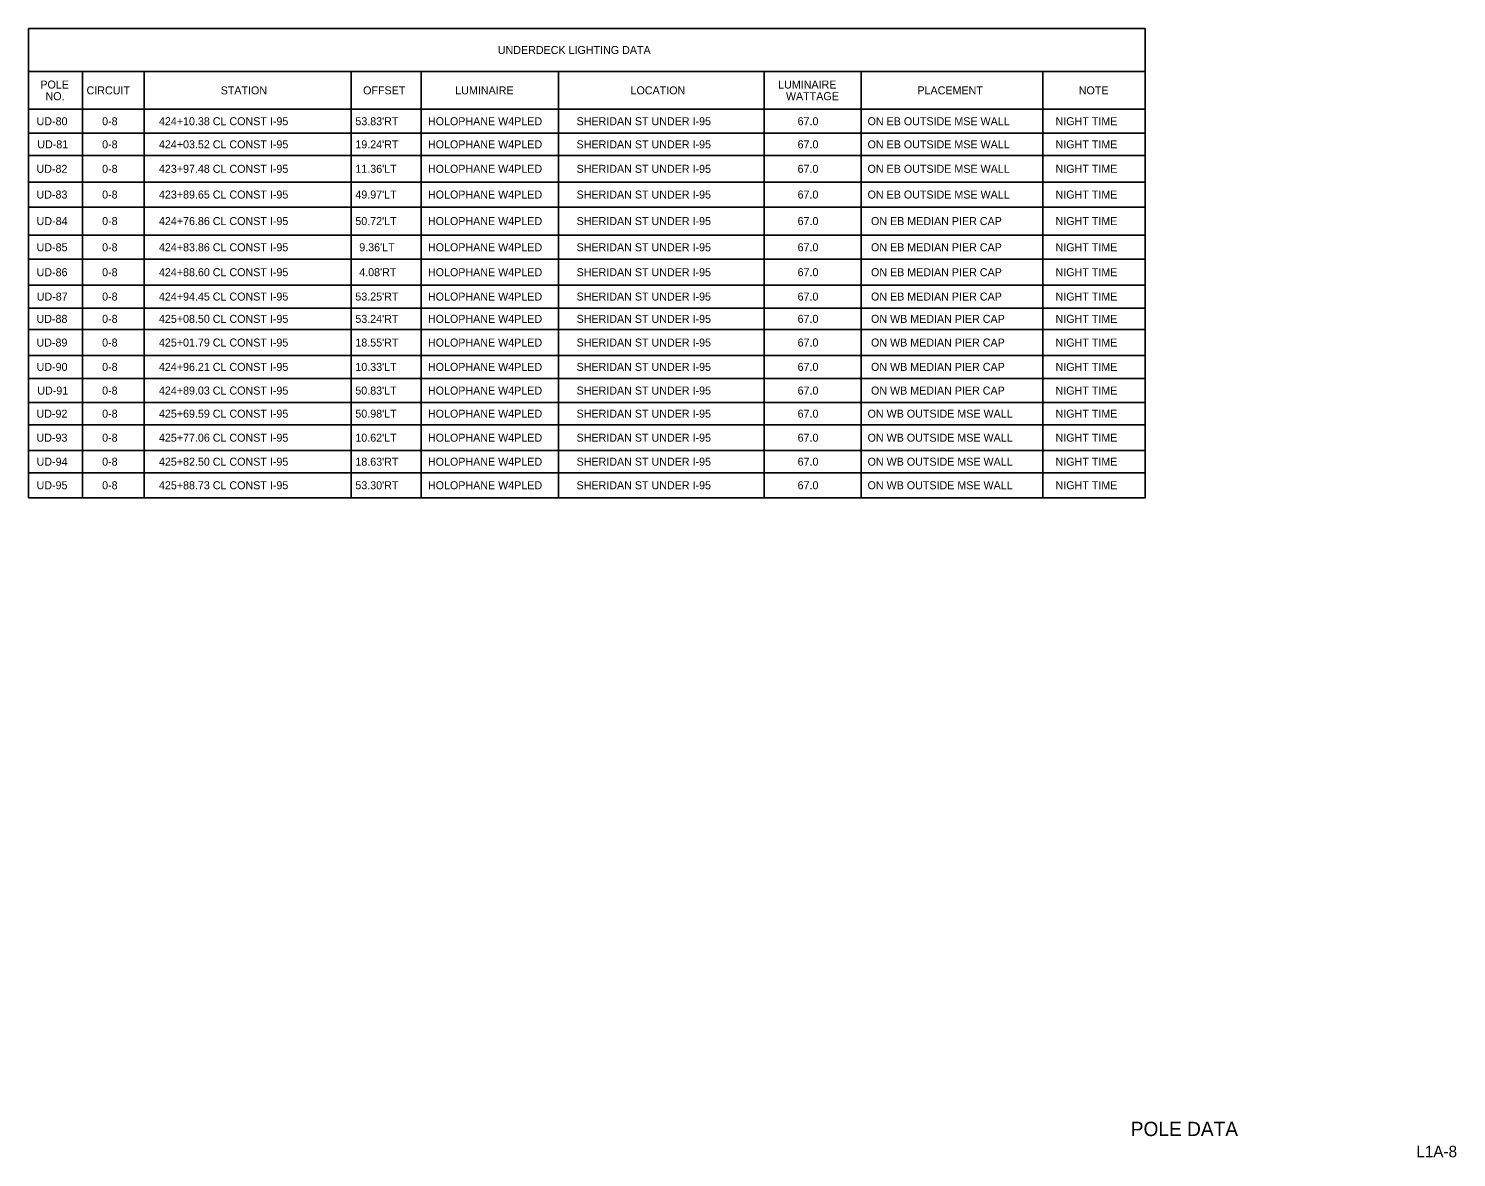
# Model space of a CAD drawing. Extents: x -816.7 to -727.6, y -2197.9 to -2187.8.
# Drawn here: x -740.07 to -727.59, y -2197.64 to -2187.77 of the extents above; entities that cross this region are included whole.
import ezdxf

# ---------------------------------------------------------------- set-up
doc = ezdxf.new("R2010")
doc.units = 0
for name, color, linetype in [('ClipBorder_dp', 7, 'Continuous'), ('MatchLines_dp', 7, 'Continuous'), ('NorthArw_dp', 7, 'Continuous'), ('Scale_dp', 7, 'Continuous'), ('SignWorkZone', 7, 'Continuous'), ('TextLabel', 7, 'Continuous')]:
    doc.layers.add(name, color=color, linetype=linetype)

msp = doc.modelspace()

# ---------------------------------------------------------------- linework, layer by layer
at = {"layer": 'MatchLines_dp'}
for p, q in [((-740.074, -2188.479), (-730.309, -2188.479)), ((-740.074, -2188.689), (-730.309, -2188.689)), ((-740.074, -2188.689), (-730.309, -2188.689)), ((-740.074, -2188.884), (-730.309, -2188.884)), ((-740.074, -2188.884), (-730.309, -2188.884)), ((-740.074, -2189.116), (-730.309, -2189.116)), ((-740.074, -2189.116), (-730.309, -2189.116)), ((-740.074, -2189.334), (-730.309, -2189.334)), ((-740.074, -2189.334), (-730.309, -2189.334)), ((-740.074, -2189.581), (-730.309, -2189.581)), ((-740.074, -2189.581), (-730.309, -2189.581)), ((-740.074, -2189.791), (-730.309, -2189.791)), ((-740.074, -2189.791), (-730.309, -2189.791)), ((-740.074, -2190.016), (-730.309, -2190.016)), ((-740.074, -2190.016), (-730.309, -2190.016)), ((-740.074, -2190.219), (-730.309, -2190.219)), ((-740.074, -2190.219), (-730.309, -2190.219)), ((-740.074, -2190.406), (-730.309, -2190.406)), ((-740.074, -2190.406), (-730.309, -2190.406)), ((-740.074, -2190.631), (-730.309, -2190.631)), ((-740.074, -2190.631), (-730.309, -2190.631)), ((-740.074, -2190.834), (-730.309, -2190.834)), ((-740.074, -2190.834), (-730.309, -2190.834)), ((-740.074, -2191.044), (-730.309, -2191.044)), ((-740.074, -2191.044), (-730.309, -2191.044)), ((-740.074, -2191.239), (-730.309, -2191.239)), ((-740.074, -2191.239), (-730.309, -2191.239)), ((-740.074, -2191.464), (-730.309, -2191.464)), ((-740.074, -2191.464), (-730.309, -2191.464)), ((-740.074, -2191.659), (-730.309, -2191.659)), ((-740.074, -2191.659), (-730.309, -2191.659))]:
    msp.add_line(p, q, dxfattribs=at)
at = {"layer": 'NorthArw_dp'}
for p, q in [((-740.074, -2187.774), (-730.309, -2187.774)), ((-740.074, -2187.774), (-740.074, -2191.876)), ((-730.309, -2187.774), (-730.309, -2191.876)), ((-740.074, -2188.149), (-730.309, -2188.149)), ((-740.074, -2188.149), (-730.309, -2188.149)), ((-731.202, -2188.149), (-731.202, -2191.876)), ((-731.202, -2188.479), (-731.202, -2191.876)), ((-740.074, -2191.876), (-730.309, -2191.876))]:
    msp.add_line(p, q, dxfattribs=at)
at = {"layer": 'Scale_dp'}
for p, q in [((-739.602, -2188.149), (-739.602, -2191.876)), ((-739.602, -2188.149), (-739.602, -2191.876)), ((-739.062, -2188.149), (-739.062, -2191.876)), ((-739.062, -2188.149), (-739.062, -2191.876)), ((-737.254, -2188.149), (-737.254, -2191.876)), ((-737.254, -2188.149), (-737.254, -2191.876)), ((-736.639, -2188.149), (-736.639, -2191.876)), ((-736.639, -2188.149), (-736.639, -2191.876)), ((-735.439, -2188.149), (-735.439, -2191.876)), ((-735.439, -2188.149), (-735.439, -2191.876)), ((-733.639, -2188.149), (-733.639, -2191.876)), ((-733.639, -2188.149), (-733.639, -2191.876)), ((-732.792, -2188.149), (-732.792, -2191.876)), ((-732.792, -2188.149), (-732.792, -2191.876)), ((-731.202, -2188.149), (-731.202, -2188.479)), ((-740.074, -2188.479), (-730.309, -2188.479))]:
    msp.add_line(p, q, dxfattribs=at)

# ---------------------------------------------------------------- texts
at = {"layer": 'ClipBorder_dp'}
for s, p in [('UNDERDECK LIGHTING DATA', (-735.97, -2187.996)), ('POLE', (-739.971, -2188.298)), ('LUMINAIRE', (-733.518, -2188.298)), ('NO.', (-739.926, -2188.4)), ('CIRCUIT', (-739.567, -2188.349)), ('STATION', (-738.394, -2188.349)), ('OFFSET', (-737.148, -2188.349)), ('LUMINAIRE', (-736.342, -2188.349)), ('LOCATION', (-734.809, -2188.349)), ('WATTAGE', (-733.45, -2188.4)), ('PLACEMENT', (-732.3, -2188.349)), ('NOTE', (-730.889, -2188.349)), ('UD-80', (-740.004, -2188.619)), ('0-8', (-739.431, -2188.619)), ('424+10.38 CL CONST I-95', (-738.934, -2188.619)), ("53.83'RT", (-737.216, -2188.619)), ('HOLOPHANE W4PLED', (-736.581, -2188.619)), ('SHERIDAN ST UNDER I-95', (-735.281, -2188.619)), ('67.0', (-733.348, -2188.619)), ('ON EB OUTSIDE MSE WALL', (-732.736, -2188.619)), ('NIGHT TIME', (-731.092, -2188.619)), ('UD-81', (-739.998, -2188.821)), ('0-8', (-739.431, -2188.821)), ('424+03.52 CL CONST I-95', (-738.934, -2188.821)), ("19.24'RT", (-737.216, -2188.821)), ('HOLOPHANE W4PLED', (-736.581, -2188.821)), ('SHERIDAN ST UNDER I-95', (-735.281, -2188.821)), ('67.0', (-733.348, -2188.821)), ('ON EB OUTSIDE MSE WALL', (-732.736, -2188.821)), ('NIGHT TIME', (-731.092, -2188.821)), ('UD-82', (-740.005, -2189.035)), ('0-8', (-739.431, -2189.035)), ('423+97.48 CL CONST I-95', (-738.934, -2189.035)), ("11.36'LT", (-737.216, -2189.035)), ('HOLOPHANE W4PLED', (-736.581, -2189.035)), ('SHERIDAN ST UNDER I-95', (-735.281, -2189.035)), ('67.0', (-733.348, -2189.035)), ('ON EB OUTSIDE MSE WALL', (-732.736, -2189.035)), ('NIGHT TIME', (-731.092, -2189.035)), ('UD-83', (-740.005, -2189.26)), ('0-8', (-739.431, -2189.26)), ('423+89.65 CL CONST I-95', (-738.934, -2189.26)), ("49.97'LT", (-737.216, -2189.26)), ('HOLOPHANE W4PLED', (-736.581, -2189.26)), ('SHERIDAN ST UNDER I-95', (-735.281, -2189.26)), ('67.0', (-733.348, -2189.26)), ('ON EB OUTSIDE MSE WALL', (-732.736, -2189.26)), ('NIGHT TIME', (-731.092, -2189.26)), ('UD-84', (-740.004, -2189.492)), ('0-8', (-739.431, -2189.492)), ('424+76.86 CL CONST I-95', (-738.934, -2189.492)), ("50.72'LT", (-737.216, -2189.492)), ('HOLOPHANE W4PLED', (-736.581, -2189.492)), ('SHERIDAN ST UNDER I-95', (-735.281, -2189.492)), ('67.0', (-733.348, -2189.492)), ('ON EB MEDIAN PIER CAP', (-732.706, -2189.492)), ('NIGHT TIME', (-731.092, -2189.492)), ('UD-85', (-740.004, -2189.721)), ('0-8', (-739.431, -2189.721)), ('424+83.86 CL CONST I-95', (-738.934, -2189.721)), ("9.36'LT", (-737.182, -2189.721)), ('HOLOPHANE W4PLED', (-736.581, -2189.721)), ('SHERIDAN ST UNDER I-95', (-735.281, -2189.721)), ('67.0', (-733.348, -2189.721)), ('ON EB MEDIAN PIER CAP', (-732.706, -2189.721)), ('NIGHT TIME', (-731.092, -2189.721)), ('UD-86', (-740.004, -2189.939)), ('0-8', (-739.431, -2189.939)), ('424+88.60 CL CONST I-95', (-738.934, -2189.939)), ("4.08'RT", (-737.182, -2189.939)), ('HOLOPHANE W4PLED', (-736.581, -2189.939)), ('SHERIDAN ST UNDER I-95', (-735.281, -2189.939)), ('67.0', (-733.348, -2189.939)), ('ON EB MEDIAN PIER CAP', (-732.706, -2189.939)), ('NIGHT TIME', (-731.092, -2189.939)), ('UD-87', (-740.003, -2190.152)), ('0-8', (-739.431, -2190.152)), ('424+94.45 CL CONST I-95', (-738.934, -2190.152)), ("53.25'RT", (-737.216, -2190.152)), ('HOLOPHANE W4PLED', (-736.581, -2190.152)), ('SHERIDAN ST UNDER I-95', (-735.281, -2190.152)), ('67.0', (-733.348, -2190.152)), ('ON EB MEDIAN PIER CAP', (-732.706, -2190.152)), ('NIGHT TIME', (-731.092, -2190.152)), ('UD-88', (-740.005, -2190.347)), ('0-8', (-739.431, -2190.347)), ('425+08.50 CL CONST I-95', (-738.934, -2190.347)), ("53.24'RT", (-737.216, -2190.347)), ('HOLOPHANE W4PLED', (-736.581, -2190.347)), ('SHERIDAN ST UNDER I-95', (-735.281, -2190.347)), ('67.0', (-733.348, -2190.347)), ('ON WB MEDIAN PIER CAP', (-732.706, -2190.347)), ('NIGHT TIME', (-731.092, -2190.347)), ('UD-89', (-740.005, -2190.554)), ('0-8', (-739.431, -2190.554)), ('425+01.79 CL CONST I-95', (-738.934, -2190.554)), ("18.55'RT", (-737.216, -2190.554)), ('HOLOPHANE W4PLED', (-736.581, -2190.554)), ('SHERIDAN ST UNDER I-95', (-735.281, -2190.554)), ('67.0', (-733.348, -2190.554)), ('ON WB MEDIAN PIER CAP', (-732.706, -2190.554)), ('NIGHT TIME', (-731.092, -2190.554)), ('UD-90', (-740.004, -2190.767)), ('0-8', (-739.431, -2190.767)), ('424+96.21 CL CONST I-95', (-738.934, -2190.767)), ("10.33'LT", (-737.216, -2190.767)), ('HOLOPHANE W4PLED', (-736.581, -2190.767)), ('SHERIDAN ST UNDER I-95', (-735.281, -2190.767)), ('67.0', (-733.348, -2190.767)), ('ON WB MEDIAN PIER CAP', (-732.706, -2190.767)), ('NIGHT TIME', (-731.092, -2190.767)), ('UD-91', (-739.998, -2190.974)), ('0-8', (-739.431, -2190.974)), ('424+89.03 CL CONST I-95', (-738.934, -2190.974)), ("50.83'LT", (-737.216, -2190.974)), ('HOLOPHANE W4PLED', (-736.581, -2190.974)), ('SHERIDAN ST UNDER I-95', (-735.281, -2190.974)), ('67.0', (-733.348, -2190.974)), ('ON WB MEDIAN PIER CAP', (-732.706, -2190.974)), ('NIGHT TIME', (-731.092, -2190.974)), ('UD-92', (-740.005, -2191.176)), ('0-8', (-739.431, -2191.176)), ('425+69.59 CL CONST I-95', (-738.934, -2191.176)), ("50.98'LT", (-737.216, -2191.176)), ('HOLOPHANE W4PLED', (-736.581, -2191.176)), ('SHERIDAN ST UNDER I-95', (-735.281, -2191.176)), ('67.0', (-733.348, -2191.176)), ('ON WB OUTSIDE MSE WALL', (-732.736, -2191.176)), ('NIGHT TIME', (-731.092, -2191.176)), ('UD-93', (-740.005, -2191.386)), ('0-8', (-739.431, -2191.386)), ('425+77.06 CL CONST I-95', (-738.934, -2191.386)), ("10.62'LT", (-737.216, -2191.386)), ('HOLOPHANE W4PLED', (-736.581, -2191.386)), ('SHERIDAN ST UNDER I-95', (-735.281, -2191.386)), ('67.0', (-733.348, -2191.386)), ('ON WB OUTSIDE MSE WALL', (-732.736, -2191.386)), ('NIGHT TIME', (-731.092, -2191.386)), ('UD-94', (-740.004, -2191.596)), ('0-8', (-739.431, -2191.596)), ('425+82.50 CL CONST I-95', (-738.934, -2191.596)), ("18.63'RT", (-737.216, -2191.596)), ('HOLOPHANE W4PLED', (-736.581, -2191.596)), ('SHERIDAN ST UNDER I-95', (-735.281, -2191.596)), ('67.0', (-733.348, -2191.596)), ('ON WB OUTSIDE MSE WALL', (-732.736, -2191.596)), ('NIGHT TIME', (-731.092, -2191.596)), ('UD-95', (-740.004, -2191.802)), ('0-8', (-739.431, -2191.802)), ('425+88.73 CL CONST I-95', (-738.934, -2191.802)), ("53.30'RT", (-737.216, -2191.802)), ('HOLOPHANE W4PLED', (-736.581, -2191.802)), ('SHERIDAN ST UNDER I-95', (-735.281, -2191.802)), ('67.0', (-733.348, -2191.802)), ('ON WB OUTSIDE MSE WALL', (-732.736, -2191.802)), ('NIGHT TIME', (-731.092, -2191.802))]:
    msp.add_text(s, height=0.07, dxfattribs=at).set_placement(p)
at = {"layer": 'SignWorkZone'}
msp.add_text('L1A-8 ', height=0.1, dxfattribs=at).set_placement((-727.937, -2197.643))
at = {"layer": 'TextLabel'}
msp.add_text('POLE DATA', height=0.125, dxfattribs=at).set_placement((-730.434, -2197.458))

doc.saveas('drawing.dxf')
